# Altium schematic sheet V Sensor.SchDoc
size 431 x 279 mm; Date: Not shown in title block; ApprovedBy: Not shown in title block; CheckedBy: Not shown in title block; Author: Not shown in title block; CompanyName: Not shown in title block; Engineer: Not shown in title block; Organization: Not shown in title block; Address1: Not shown in title block; Address2: Not shown in title block; Address3: Not shown in title block; Address4: Not shown in title block; DocumentNumber: 1; Revision: Use project parameter SCH_Rev; SheetNumber: 4; SheetTotal: 6; PageSetup: Record=PageOptions¦CenterHorizontal=True¦CenterVertical=True¦PrintScale=1.00¦XCorrection=1.00¦YCorrection=1.00¦PrintKind=0¦BorderSize=5000000¦LeftOffset=0¦BottomOffset=0¦Orientation=2¦PaperLength=1000¦PaperWidth=1000¦Scale=100¦PaperSource=15¦PrintQuality=600¦MediaType=1¦DitherType=10¦PaperKind=Letter¦PrintScaleMode=1
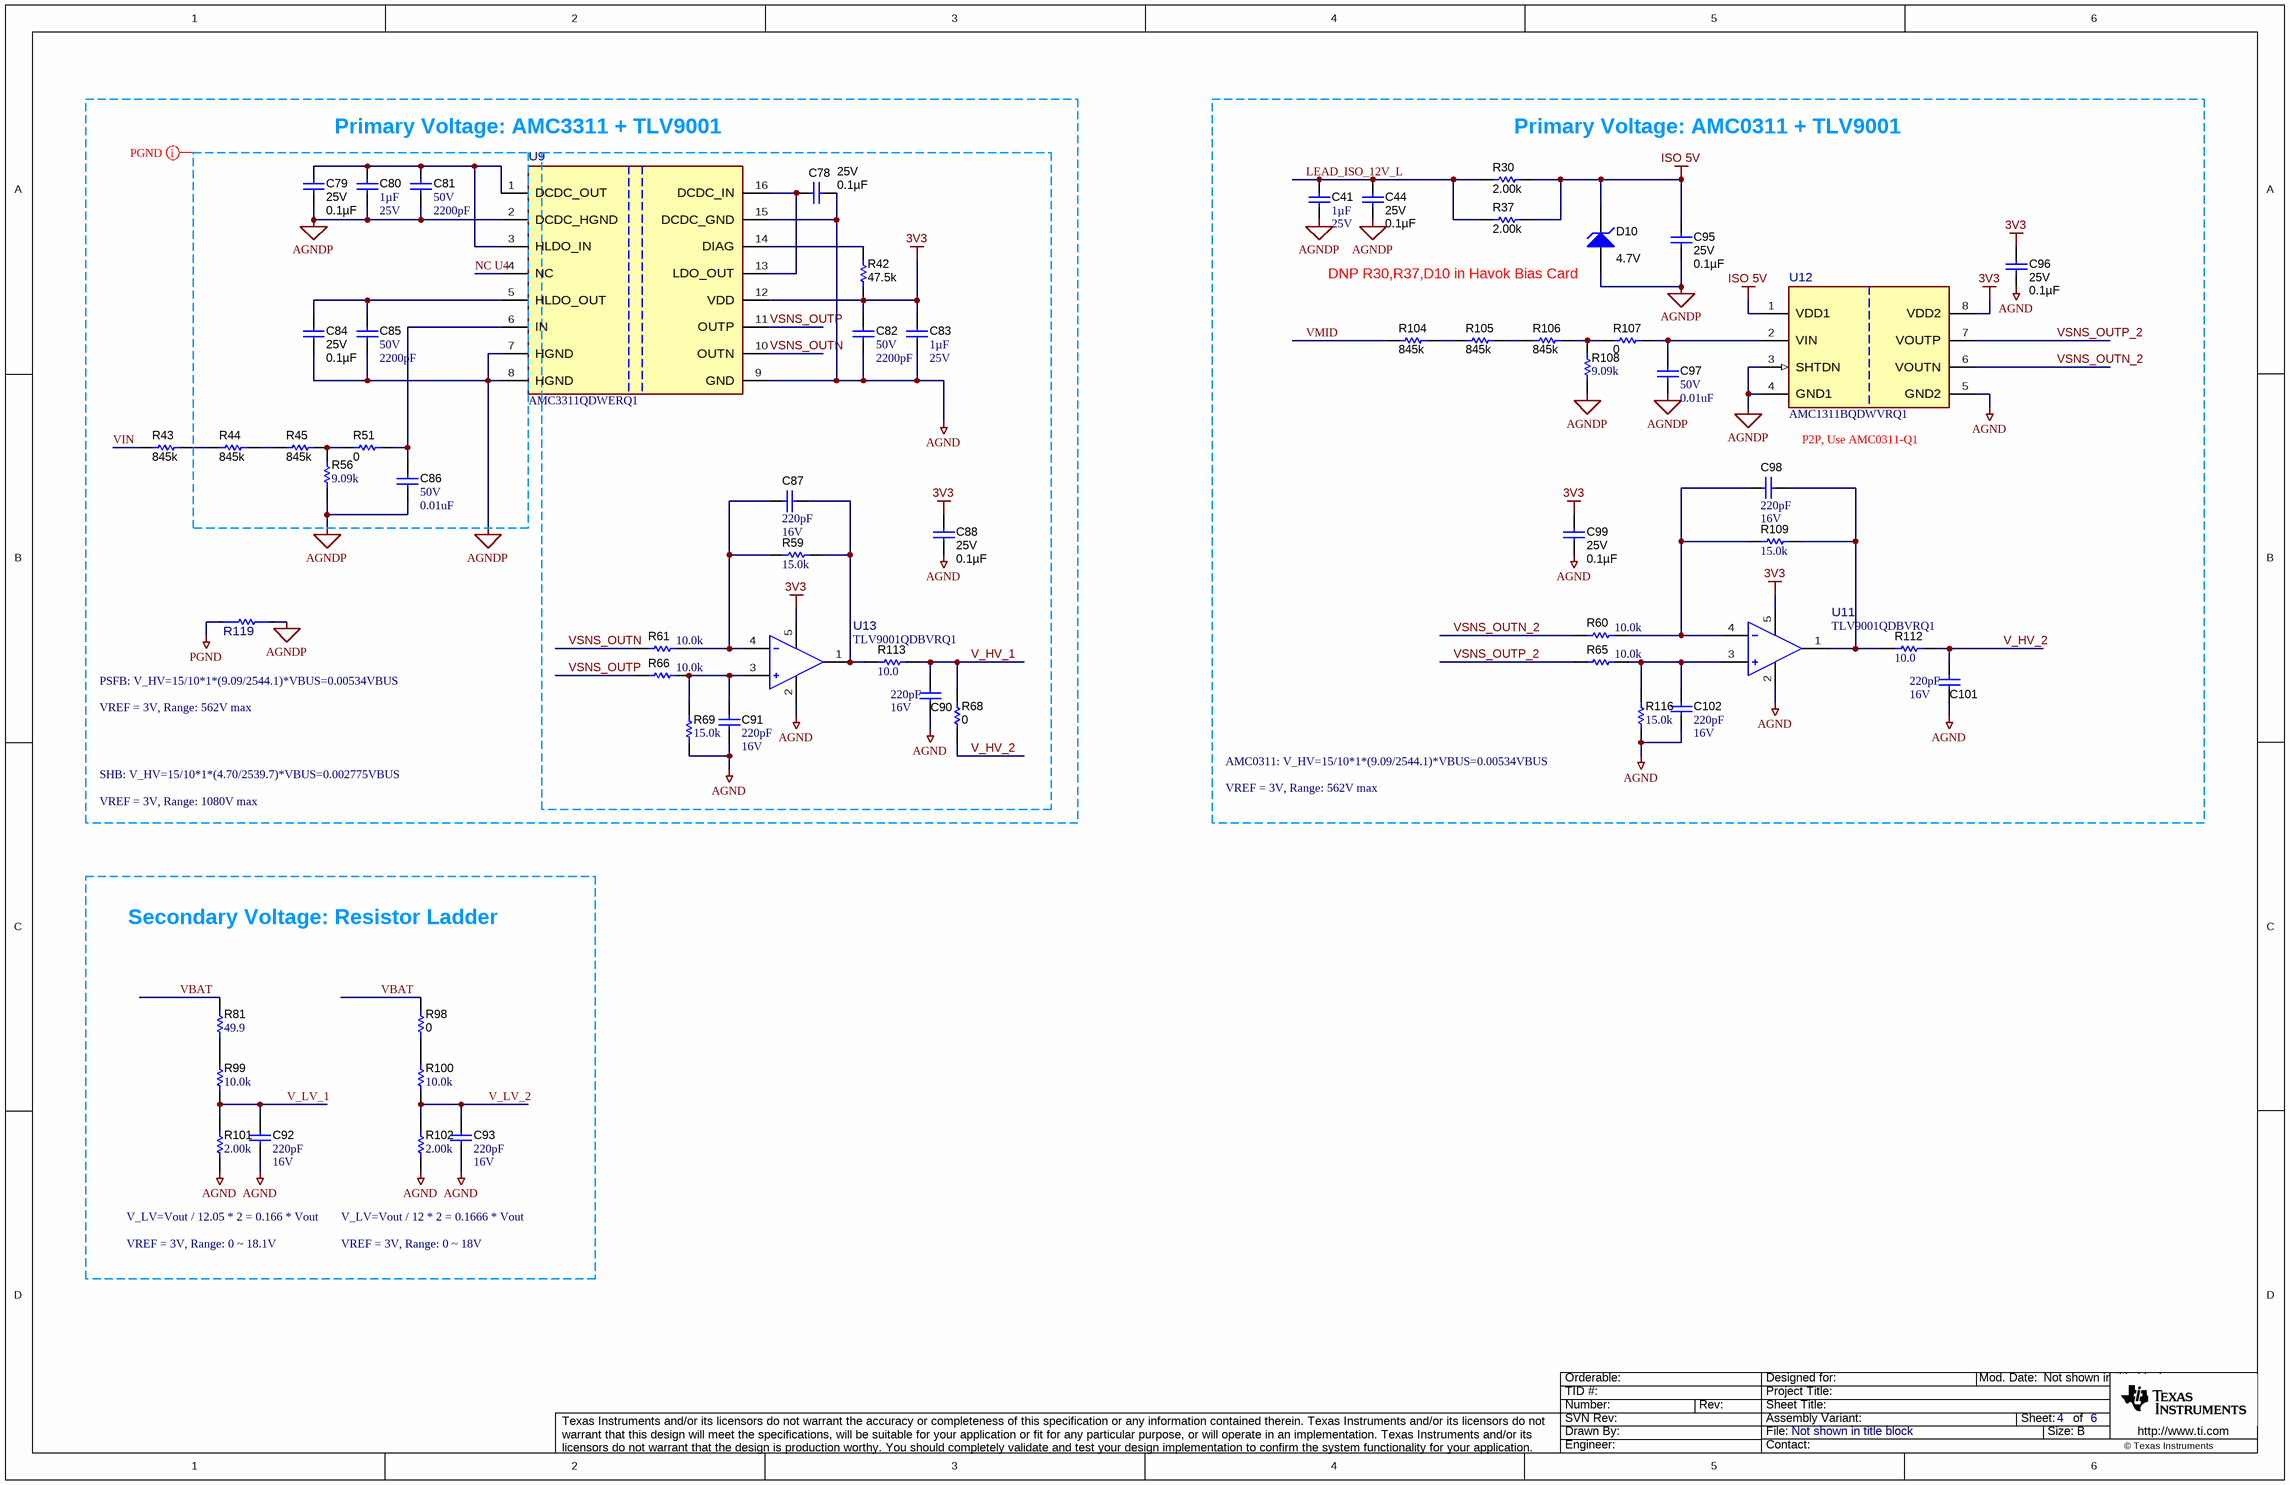
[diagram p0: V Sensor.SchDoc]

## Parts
C41  Cap_F: 1µF  VDC_V: 25V  [0603S]  (hidden comment: CGA3E1X7R1E105K080AC)
C44  VDC_V: 25V  ValueDisplayed: 0.1µF  [0402]  (hidden comment: CGA2B3X7R1E104K050BB)
C78  VDC_V: 25V  ValueDisplayed: 0.1µF  [0402]  (hidden comment: CGA2B3X7R1E104K050BB)
C79  VDC_V: 25V  ValueDisplayed: 0.1µF  [0402]  (hidden comment: CGA2B3X7R1E104K050BB)
C80  Cap_F: 1µF  VDC_V: 25V  [0603S]  (hidden comment: CGA3E1X7R1E105K080AC)
C81  VDC_V: 50V  ValueDisplayed: 2200pF  [0402]  (hidden comment: GCM155R71H222KA37D)
C82  VDC_V: 50V  ValueDisplayed: 2200pF  [0402]  (hidden comment: GCM155R71H222KA37D)
C83  Cap_F: 1µF  VDC_V: 25V  [0603S]  (hidden comment: CGA3E1X7R1E105K080AC)
C84  VDC_V: 25V  ValueDisplayed: 0.1µF  [0402]  (hidden comment: CGA2B3X7R1E104K050BB)
C85  VDC_V: 50V  ValueDisplayed: 2200pF  [0402]  (hidden comment: GCM155R71H222KA37D)
C86  VDC_V: 50V  ValueDisplayed: 0.01uF  [0402]  (hidden comment: CGA2B3X7R1H103K050BB)
C87  ValueDisplayed: 220pF  VDC_V: 16V  [0402]  (hidden comment: AC0402KRX7R7BB221)
C88  VDC_V: 25V  ValueDisplayed: 0.1µF  [0402]  (hidden comment: CGA2B3X7R1E104K050BB)
C90  ValueDisplayed: 220pF  VDC_V: 16V  [0402]  (hidden comment: AC0402KRX7R7BB221)
C91  ValueDisplayed: 220pF  VDC_V: 16V  [0402]  (hidden comment: AC0402KRX7R7BB221)
C92  ValueDisplayed: 220pF  VDC_V: 16V  [0402]  (hidden comment: AC0402KRX7R7BB221)
C93  ValueDisplayed: 220pF  VDC_V: 16V  [0402]  (hidden comment: AC0402KRX7R7BB221)
C95  VDC_V: 25V  ValueDisplayed: 0.1µF  [0402]  (hidden comment: CGA2B3X7R1E104K050BB)
C96  VDC_V: 25V  ValueDisplayed: 0.1µF  [0402]  (hidden comment: CGA2B3X7R1E104K050BB)
C97  VDC_V: 50V  ValueDisplayed: 0.01uF  [0402]  (hidden comment: CGA2B3X7R1H103K050BB)
C98  ValueDisplayed: 220pF  VDC_V: 16V  [0402]  (hidden comment: AC0402KRX7R7BB221)
C99  VDC_V: 25V  ValueDisplayed: 0.1µF  [0402]  (hidden comment: CGA2B3X7R1E104K050BB)
C101  ValueDisplayed: 220pF  VDC_V: 16V  [0402]  (hidden comment: AC0402KRX7R7BB221)
C102  ValueDisplayed: 220pF  VDC_V: 16V  [0402]  (hidden comment: AC0402KRX7R7BB221)
D10  value 4.7V  [SOD-523]  (hidden comment: EDZVFHT2R4.7B)
R30  ValueDisplayed: 2.00k  [0603]  (hidden comment: CRCW06032K00FKEA)
R37  ValueDisplayed: 2.00k  [0603]  (hidden comment: CRCW06032K00FKEA)
R42  ValueDisplayed: 47.5k  [0402]  (hidden comment: CRCW040247K5FKED)
R43  ValueDisplayed: 845k  [1206]  (hidden comment: ERJ-8ENF8453V)
R44  ValueDisplayed: 845k  [1206]  (hidden comment: ERJ-8ENF8453V)
R45  ValueDisplayed: 845k  [1206]  (hidden comment: ERJ-8ENF8453V)
R51  ValueDisplayed: 0  [0402]  (hidden comment: CRCW04020000Z0ED)
R56  ValueDisplayed: 9.09k  [1206]  (hidden comment: CRCW12069K09FKEA)
R59  ValueDisplayed: 15.0k  [0402]  (hidden comment: CRCW040215K0FKED)
R60  ValueDisplayed: 10.0k  [0402]  (hidden comment: RK73H1ETTP1002F)
R61  ValueDisplayed: 10.0k  [0402]  (hidden comment: RK73H1ETTP1002F)
R65  ValueDisplayed: 10.0k  [0402]  (hidden comment: RK73H1ETTP1002F)
R66  ValueDisplayed: 10.0k  [0402]  (hidden comment: RK73H1ETTP1002F)
R68  ValueDisplayed: 0  [0402]  (hidden comment: CRCW04020000Z0ED)
R69  ValueDisplayed: 15.0k  [0402]  (hidden comment: CRCW040215K0FKED)
R81  ValueDisplayed: 49.9  [0402]  (hidden comment: CRCW040249R9FKED)
R98  ValueDisplayed: 0  [0402]  (hidden comment: CRCW04020000Z0ED)
R99  ValueDisplayed: 10.0k  [0402]  (hidden comment: RK73H1ETTP1002F)
R100  ValueDisplayed: 10.0k  [0402]  (hidden comment: RK73H1ETTP1002F)
R101  ValueDisplayed: 2.00k  [0402]  (hidden comment: ERJ-2RKF2001X)
R102  ValueDisplayed: 2.00k  [0402]  (hidden comment: ERJ-2RKF2001X)
R104  ValueDisplayed: 845k  [1206]  (hidden comment: ERJ-8ENF8453V)
R105  ValueDisplayed: 845k  [1206]  (hidden comment: ERJ-8ENF8453V)
R106  ValueDisplayed: 845k  [1206]  (hidden comment: ERJ-8ENF8453V)
R107  ValueDisplayed: 0  [0402]  (hidden comment: CRCW04020000Z0ED)
R108  ValueDisplayed: 9.09k  [1206]  (hidden comment: CRCW12069K09FKEA)
R109  ValueDisplayed: 15.0k  [0402]  (hidden comment: CRCW040215K0FKED)
R112  ValueDisplayed: 10.0  [0402]  (hidden comment: RMCF0402JT10R0)
R113  ValueDisplayed: 10.0  [0402]  (hidden comment: RMCF0402JT10R0)
R116  ValueDisplayed: 15.0k  [0402]  (hidden comment: CRCW040215K0FKED)
R119  RMCF1206ZT0R00  [FP-RMCF1206ZT0R00_1206-MFG]  (value not drawn)
U9  AMC3311QDWERQ1  [DWE0016A-MFG]
U11  TLV9001QDBVRQ1  [DBV0005A-MFG]
U12  AMC1311BQDWVRQ1  [DWV0008A-MFG]
U13  TLV9001QDBVRQ1  [DBV0005A-MFG]

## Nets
3V3: C82.1 C83.1 C88.1 C96.1 C99.1 R42.1 U9.12(VDD) U11.5(V+) U12.8(VDD2) U13.5(V+)
AGND: C78.2 C82.2 C83.2 C88.2 C90.2 C91.2 C92.2 C93.2 C96.2 C99.2 C101.2 C102.2 R69.1 R101.1 R102.1 R116.1 U9.9(GND) U9.15(DCDC_GND) U11.2(V-) U12.5(GND2) U13.2(V-)
AGNDP: C41.2 C44.2 C79.2 C80.2 C81.2 C84.2 C85.2 C86.2 C95.2 C97.2 D10.2(A) R56.1 R108.1 R119.2 U9.2(DCDC_HGND) U9.7(HGND) U9.8(HGND) U12.3(SHTDN) U12.4(GND1)
ISO 5V: C95.1 D10.1(K) R30.2 R37.2 U12.1(VDD1)
PGND: R119.1
LEAD_ISO_12V_L: C41.1 C44.1 R30.1 R37.1
NC U4: U9.4(NC)
V_HV_1: C90.1 R68.1 R113.2
V_HV_2: C101.1 R68.2 R112.2
V_LV_1: C92.1 R99.1 R101.2
V_LV_2: C93.1 R100.1 R102.2
VBAT: R81.2 R98.2
VIN: R43.1
VMID: R104.1
VSNS_OUTN: R61.2 U9.10(OUTN)
VSNS_OUTN_2: R60.2 U12.6(VOUTN)
VSNS_OUTP: R66.2 U9.11(OUTP)
VSNS_OUTP_2: R65.2 U12.7(VOUTP)
NetC78_1: C78.1 U9.13(LDO_OUT) U9.16(DCDC_IN)
NetC79_1: C79.1 C80.1 C81.1 U9.1(DCDC_OUT) U9.3(HLDO_IN)
NetC84_1: C84.1 C85.1 U9.5(HLDO_OUT)
NetC86_1: C86.1 R51.1 U9.6(IN)
NetC87_1: C87.1 R59.1 R61.1 U13.4(IN-)
NetC87_2: C87.2 R59.2 R113.1 U13.1(OUT)
NetC91_1: C91.1 R66.1 R69.2 U13.3(IN+)
NetC97_1: C97.1 R107.1 U12.2(VIN)
NetC98_1: C98.1 R60.1 R109.1 U11.4(IN-)
NetC98_2: C98.2 R109.2 R112.1 U11.1(OUT)
NetC102_1: C102.1 R65.1 R116.2 U11.3(IN+)
NetR42_2: R42.2 U9.14(DIAG)
NetR43_2: R43.2 R44.1
NetR44_2: R44.2 R45.1
NetR45_2: R45.2 R51.2 R56.2
NetR81_1: R81.1 R99.2
NetR98_1: R98.1 R100.2
NetR104_2: R104.2 R105.1
NetR105_2: R105.2 R106.1
NetR106_2: R106.2 R107.2 R108.2

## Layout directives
net class PGND: 3V3, AGND, AGNDP, NC U4, PGND, V_HV_1, V_HV_2, VIN, VSNS_OUTN, VSNS_OUTP

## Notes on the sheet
- Primary Voltage: AMC3311 + TLV9001
- (near R30) Primary Voltage: AMC0311 + TLV9001
- DNP R30,R37,D10 in Havok Bias Card
- P2P, Use AMC0311-Q1
- PSFB: V_HV=15/10*1*(9.09/2544.1)*VBUS=0.00534VBUS
- VREF = 3V, Range: 562V max
- AMC0311: V_HV=15/10*1*(9.09/2544.1)*VBUS=0.00534VBUS
- SHB: V_HV=15/10*1*(4.70/2539.7)*VBUS=0.002775VBUS
- VREF = 3V, Range: 1080V max
- Secondary Voltage: Resistor Ladder
- V_LV=Vout / 12.05 * 2 = 0.166 * Vout
- V_LV=Vout / 12 * 2 = 0.1666 * Vout
- VREF = 3V, Range: 0 ~ 18.1V
- VREF = 3V, Range: 0 ~ 18V

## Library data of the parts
C41 C80 C83 = CMP-0076705-3: CAP, CERM, 1 µF, 25 V,+/- 10%, X7R, AEC-Q200 Grade 1, 0603; Manufacturer: TDK; SizeAreaWB_mm2: 4.68; SizeArea_mm2: 1.28; AEC Qualified: Y; AEC Category: Q200; Value: 1uF; TaMax_C: 125°C; SizeZ_mm: 1.0; AEC Grade: 1; Polarized: N; TaMin_C: -55°C; SizeY_mm: 0.8; U/M: EA; SizeX_mm: 1.6; Cap_Case: 1.6x0.8x0.8mm
C44 C78 C79 C84 C88 C95 C96 C99 = CMP-0080610-1: CAP, CERM, 0.1 µF, 25 V,+/- 10%, X7R, AEC-Q200 Grade 1, 0402; Manufacturer: TDK; TaMin_C: -55°C; Polarized: N; SizeAreaWB_mm2: 3; U/M: EA; Value: 0.1uF; TaMax_C: 125°C; SizeZ_mm: 0.6; SizeX_mm: 1; SizeY_mm: 0.5; AEC Qualified: Y; Cap_F: 100nF; AEC Category: Q200
C81 C82 C85 = CMP-0006357-2: CAP, CERM, 2200 pF, 50 V, +/- 10%, X7R, AEC-Q200 Grade 1, 0402; Manufacturer: MuRata; TaMin_C: -55°C; Polarized: N; SizeAreaWB_mm2: 3; Value1: Unknown; U/M: EA; Value: 2200pF; TaMax_C: 125°C; SizeZ_mm: 0.6; SizeX_mm: 1; SizeY_mm: 0.5; AEC Qualified: Y; Cap_F: 2.2nF; AEC Category: Q200
C86 C97 = CMP-0006324-2: CAP, CERM, 0.01 uF, 50 V, +/- 10%, X7R, AEC-Q200 Grade 1, 0402; Manufacturer: TDK; TaMin_C: -55°C; ESR_ohm: 3.33065d; Polarized: N; SizeAreaWB_mm2: 3; Value1: 0.333065 ohm; U/M: EA; Value: 0.01uF; TaMax_C: 125°C; SizeZ_mm: 0.6; SizeX_mm: 1; SizeY_mm: 0.5; AEC Qualified: Y; Cap_F: 10nF; IRMS_A: 3.23373dA; AEC Category: Q200
C87 C90-C93 C98 C101 C102 = CMP-0085176-1: CAP, CERM, 220 pF, 16 V,+/- 10%, X7R, AEC-Q200 Grade 1, 0402; Manufacturer: Yageo; Value: 220pF; SizeZ_mm: 0.6; TaMin_C: -55°C; AEC Category: Q200; AEC Qualified: Y; SizeY_mm: 0.5; SizeAreaWB_mm2: 3; AEC Grade: 1; U/M: EA; TaMax_C: 125°C; Polarized: N
D10 = CMP-0005910-2: Diode, Zener, 4.7 V, 150 mW, AEC-Q101, SOD-523; Manufacturer: Rohm; Power_W: 150mW; SizeAreaWB_mm2: 5.13; Value1: 0.15W; U/M: EA; SizeZ_mm: 0.65; SizeX_mm: 1.7; SizeY_mm: 0.9; SizeArea_mm2: 1.53; AEC Qualified: Y; AEC Category: Q101
R30 R37 = CMP-0022268-4: RES, 2.00 k, 1%, 0.1 W, AEC-Q200 Grade 0, 0603; Manufacturer: Vishay-Dale; Power_W: 100mW; TempCo: 100 ppm/C; Value_Code: 2k00; Value: 2.00k; EIA_Code: E96; Res_ohm: 2k; SizeX_mm: 1.6; SizeY_mm: 0.8; SizeZ_mm: 1; Value2: 0.1W; SizeArea_mm2: 1.28; AEC Qualified: Y; VDC_V: 75V; AEC Category: Q200; AEC Grade: 0
R42 = CMP-0026395-2: RES, 47.5 k, 1%, 0.063 W, AEC-Q200 Grade 0, 0402; Manufacturer: Vishay-Dale; Power_W: 63mW; TempCo: 100 ppm/C; Value_Code: 47k5; Value: 47.5k; EIA_Code: E96; SizeX_mm: 1; SizeY_mm: 0.5; SizeZ_mm: 0.6; Value2: 0.063W; AEC Qualified: Y; VDC_V: 50V; AEC Category: Q200; AEC Grade: 0
R43-R45 R104-R106 = CMP-0017741-3: RES, 845 k, 1%, 0.25 W, AEC-Q200 Grade 0, 1206; Manufacturer: Panasonic; Power_W: 250mW; TempCo: 100 ppm/C; Value: 845k; EIA_Code: E96; SizeX_mm: 3.2; SizeY_mm: 1.6; SizeZ_mm: 1.35; Value2: 0.25W; SizeArea_mm2: 5.12; AEC Qualified: Y; VDC_V: 200V; AEC Category: Q200; AEC Grade: 0; SizeAreaWB_mm2: 10.92
R51 R68 R98 R107 = CMP-0026822-3: RES, 0, 5%, 0.063 W, AEC-Q200 Grade 0, 0402; Manufacturer: Vishay-Dale; Power_W: 63mW; TempCo: 200 ppm/C; Value_Code: 0000; Value: 0; EIA_Code: E24; SizeX_mm: 1; SizeY_mm: 0.5; SizeZ_mm: 0.6; Value2: 0.063W; AEC Qualified: Y; VDC_V: 50V; AEC Category: Q200
R56 R108 = CMP-0017234-3: RES, 9.09 k, 1%, 0.25 W, AEC-Q200 Grade 0, 1206; Manufacturer: Vishay-Dale; Power_W: 250mW; TempCo: 100 ppm/C; Value_Code: 9k09; Value: 9.09k; EIA_Code: E96; SizeX_mm: 3.2; SizeY_mm: 1.6; SizeZ_mm: 1.35; Value2: 0.25W; SizeArea_mm2: 5.12; AEC Qualified: Y; VDC_V: 200V; AEC Category: Q200; AEC Grade: 0
R59 R69 R109 R116 = CMP-0026027-3: RES, 15.0 k, 1%, 0.063 W, AEC-Q200 Grade 0, 0402; Manufacturer: Vishay-Dale; Power_W: 63mW; TempCo: 100 ppm/C; Value_Code: 15k0; Value: 15.0k; EIA_Code: E96; Res_ohm: 15k; SizeX_mm: 1; SizeY_mm: 0.5; SizeZ_mm: 0.6; Value2: 0.063W; AEC Qualified: Y; VDC_V: 50V; AEC Category: Q200; AEC Grade: 0
R60 R61 R65 R66 R99 R100 = CMP-0026748-1: RES, 10.0 k, 1%, 0.063 W, AEC-Q200 Grade 0, 0402; Manufacturer: KOA Speer; Power_W: 63mW; TempCo: 100 ppm/C; Value_Code: 10k0; U/M: EA; Value: 10.0k; EIA_Code: E96; Res_ohm: 10k; SizeX_mm: 1; SizeY_mm: 0.5; SizeZ_mm: 0.6; Value2: 0.063W; AEC Qualified: Y; VDC_V: 50V; AEC Grade: 0; AEC Category: Q200
R81 = CMP-0026404-2: RES, 49.9, 1%, 0.063 W, AEC-Q200 Grade 0, 0402; Manufacturer: Vishay-Dale; Power_W: 63mW; TempCo: 100 ppm/C; Value_Code: 49R9; Value: 49.9; EIA_Code: E96; SizeX_mm: 1; SizeY_mm: 0.5; SizeZ_mm: 0.6; Value2: 0.063W; AEC Qualified: Y; VDC_V: 50V; AEC Category: Q200; AEC Grade: 0
R101 R102 = CMP-0026676-1: RES, 2.00 k, 1%, 0.1 W, AEC-Q200 Grade 0, 0402; Manufacturer: Panasonic; Power_W: 100mW; TempCo: 100 ppm/C; Value_Code: 2k00; U/M: EA; Value: 2.00k; EIA_Code: E96; Res_ohm: 2k; SizeX_mm: 1; SizeY_mm: 0.5; SizeZ_mm: 0.6; Value2: 0.1W; AEC Qualified: Y; VDC_V: 50V; AEC Grade: 0; AEC Category: Q200
R112 R113 = CMP-0026764-1: RES, 10.0, 1%, 0.063 W, AEC-Q200 Grade 0, 0402; Manufacturer: Stackpole Electronics Inc; Power_W: 63mW; TempCo: 100 ppm/C; Value_Code: 10R0; U/M: EA; Value: 10.0; EIA_Code: E96; Res_ohm: 10; SizeX_mm: 1; SizeY_mm: 0.5; SizeZ_mm: 0.6; Value2: 0.063W; AEC Qualified: Y; AEC Grade: 0; AEC Category: Q200
R119 = CMP-0093609-1: 0Ω ±0 0.25W 1206 Thick Film Chip Resistor AEC-Q200 compliant; Manufacturer: Stackpole Electronics; Res_ohm: 0; AEC Qualified: Yes; Value: 0; VDC_V: 200V; AEC Grade: Grade 0; Power_W: 250mW; SizeZ_mm: 0.7mm
U9 = CMP-0121212-1: Automotive, 0 to 2-V input, precision reinforced isolated amplifier with integrated DC/DC converter 16-SOIC -40 to 125; Manufacturer: Texas Instruments; SizeZ_mm: 2.65mm; AEC Qualified: Yes; AEC Grade: Grade 1; Bandwidth: 275kHz; Input Bias Current: 0.0035uA; Input Offset Voltage: 0.1mV; Max Supply Voltage: 5.5V; Min Supply Voltage: 3V; Nominal Supply Current: 28.5-36.5mA; Number Of Channels: 1; Output Current Per Channel: 14mA; Response Time: 0.6ms; Standoff Height: 0.1mm; TaMax_C: +125°C; TaMin_C: -40°C; TJmax_C: +150°C; Voltage Gain: 0.001V/mV
U11 U13 = CMP-0120546-1: Automotive, single-channel, 5.5-V 1-MHz rail-to-rail input and output operational amplifier 5-SOT-23 -40 to 125; Manufacturer: Texas Instruments; SizeZ_mm: 1.45mm; AEC Qualified: Yes; AEC Grade: Grade 1; Gain Bandwidth: 1MHz; Input Bias Current: 0.000005uA; Input Offset Voltage: 0.4mV; Max Dual Supply Voltage: 2.75V; Max Supply Voltage: 5.5V; Min Dual Supply Voltage: 900mV; Min Supply Voltage: 1.8V; Nominal Supply Current: 60uA; Number Of Channels: 1; Output Current Per Channel: 40mA; Response Time: 3us; Standoff Height: 0mm; TaMax_C: +125°C; TaMin_C: -40°C; TJmax_C: +150°C; Voltage Gain: 130dB
U12 = CMP-0090465-1: Automotive 2-V input, reinforced isolated amplifier with high CMTI for voltage sensing 8-SOIC -40 to 125; Manufacturer: Texas Instruments; Input Offset Voltage: -1.1mV; Response Time: 50us; Standoff Height: 0.36mm; Nominal Supply Current: 5.3-7.1mA; AEC Grade: Grade 1; Number Of Channels: 1; TJmax_C: +150°C; AEC Qualified: Yes; Max Supply Voltage: 5.5V; SizeZ_mm: 2.8mm; Input Bias Current: 0.0035uA; TaMax_C: +125°C; TaMin_C: -40°C; Output Current Per Channel: 13mA; Min Supply Voltage: 3V; Bandwidth: 275kHz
